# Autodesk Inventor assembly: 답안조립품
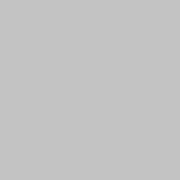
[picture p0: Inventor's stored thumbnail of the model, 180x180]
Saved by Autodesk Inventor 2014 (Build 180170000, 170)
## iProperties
Created: 2016-01
Part Number: 답안조립품
Document SubType Name: Assembly
Designer: basic
Author: basic
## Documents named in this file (1)
- C:\Users\basic\Desktop\460106V1010\답안조립품.iam
